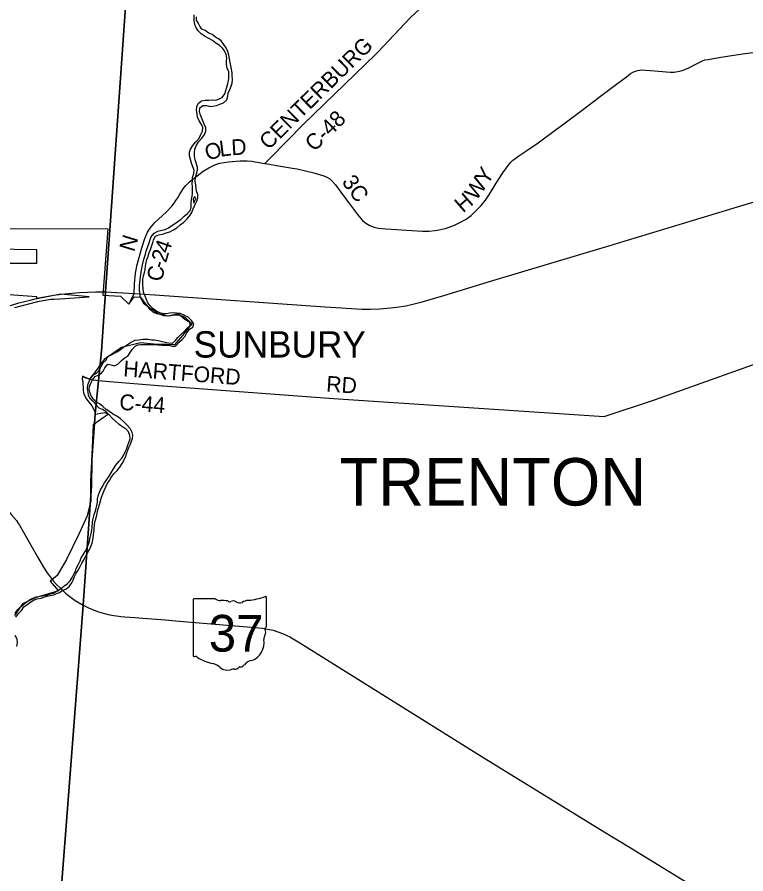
# Model space of a CAD drawing. Extents: x 1674899 to 2057726, y 653888 to 988278.
# Drawn here: x 1869524 to 1883353, y 809139 to 825391 of the extents above; entities that cross this region are included whole.
import ezdxf

# ---------------------------------------------------------------- set-up
doc = ezdxf.new("R2010")
doc.units = 0
for name, color, linetype in [('GM_X_Corporation', 7, 'Continuous'), ('GM_X_Corporation_Text', 7, 'Continuous'), ('GM_X_County_Road', 7, 'Continuous'), ('GM_X_County_Road_Text', 7, 'Continuous'), ('GM_X_Major_River', 7, 'Continuous'), ('GM_X_State_Location', 7, 'Continuous'), ('GM_X_State_Route', 7, 'Continuous'), ('GM_X_State_Shield', 7, 'Continuous'), ('GM_X_Township', 7, 'Continuous'), ('GM_X_Township_Text', 7, 'Continuous'), ('GM_X_US_Route', 7, 'Continuous'), ('SH_Data', 7, 'Continuous')]:
    doc.layers.add(name, color=color, linetype=linetype)

msp = doc.modelspace()

# ---------------------------------------------------------------- linework, layer by layer
at = {"layer": 'GM_X_Corporation'}
for points in [[(1868600, 821384), (1871245, 821376), (1871152, 820118), (1871483, 820096), (1871642, 819946), (1871748, 820085), (1871861, 820081), (1871921, 819965), (1872043, 819876), (1872199, 819766), (1872392, 819723), (1872582, 819770), (1872706, 819663), (1872848, 819582), (1872764, 819484), (1872661, 819350), (1872513, 819172), (1872369, 819183), (1872118, 819190), (1871863, 819214), (1871502, 819125), (1871177, 818898), (1870906, 818525), (1870848, 818543), (1870767, 818577), (1870760, 818526), (1870768, 818476), (1870779, 818314), (1870786, 818263), (1870803, 818212), (1870841, 818142), (1870892, 818081), (1870941, 818016), (1870984, 817932), (1871003, 817857), (1871186, 817888), (1871257, 817859), (1870965, 817659), (1870940, 817085), (1870914, 816591), (1870918, 816409), (1870920, 816216), (1870850, 815933), (1870694, 815581), (1870461, 815102), (1870281, 814797), (1870152, 814693), (1870300, 814517), (1870310, 814507), (1869865, 814374), (1869626, 814263), (1869472, 814042)], [(1869039, 820726), (1869899, 820726), (1869899, 820974), (1868600, 820997)], [(1869480, 819883), (1869917, 819994), (1870158, 820041), (1870228, 820041), (1870333, 820049), (1870889, 820088), (1870356, 820135), (1869899, 820044), (1869899, 820085), (1868844, 820159)]]:
    msp.add_lwpolyline(points, dxfattribs=at)
at = {"layer": 'GM_X_County_Road'}
for points in [[(1874227, 822615), (1874317, 822710), (1874959, 823358), (1876327, 824682), (1876365, 824720), (1876987, 825381), (1877524, 825893)], [(1872724, 822198), (1872792, 822267), (1872943, 822383), (1873056, 822467), (1873160, 822533), (1873276, 822590), (1873373, 822621), (1873532, 822646), (1873759, 822667), (1873891, 822665), (1873977, 822657), (1874044, 822647), (1874227, 822615), (1874315, 822599), (1874444, 822579), (1874557, 822560), (1874752, 822527), (1874836, 822512), (1875152, 822435), (1875346, 822380), (1875416, 822349), (1875458, 822321), (1875497, 822287), (1875565, 822207), (1875667, 822073), (1875831, 821849), (1875981, 821648), (1876039, 821575), (1876079, 821533), (1876143, 821482), (1876217, 821438), (1876297, 821406), (1876374, 821389), (1876519, 821376), (1876727, 821364), (1876913, 821349), (1877214, 821328), (1877336, 821330), (1877454, 821342), (1877534, 821356), (1877649, 821382), (1877722, 821406), (1877821, 821445), (1877928, 821496), (1878043, 821558), (1878138, 821626), (1878219, 821701), (1878331, 821818), (1878413, 821920), (1878486, 822032), (1878616, 822239), (1878743, 822436), (1878811, 822535), (1878842, 822578), (1878871, 822613), (1878895, 822642), (1878934, 822678), (1878967, 822704), (1879044, 822758), (1879197, 822860), (1879414, 823008), (1879735, 823245), (1879901, 823370), (1880245, 823625), (1880570, 823871), (1880847, 824079), (1881042, 824227), (1881087, 824259), (1881166, 824319), (1881210, 824345), (1881256, 824365), (1881305, 824380), (1881378, 824389), (1881448, 824388), (1881628, 824373), (1881838, 824352), (1881925, 824346), (1881993, 824349), (1882027, 824352), (1882091, 824364), (1882142, 824378), (1882259, 824424), (1882312, 824450), (1882368, 824481), (1882502, 824549), (1882531, 824563), (1882576, 824578), (1882637, 824590), (1882881, 824632), (1883086, 824662), (1883290, 824696), (1883493, 824720)], [(1871742, 820151), (1871742, 820151), (1871754, 820333), (1871771, 820532), (1871780, 820600), (1871796, 820672), (1871893, 821017), (1871942, 821170), (1871996, 821311), (1872051, 821390), (1872132, 821486), (1872206, 821558), (1872281, 821630), (1872352, 821694), (1872457, 821804), (1872502, 821861), (1872537, 821910), (1872571, 821965), (1872610, 822031), (1872673, 822132), (1872724, 822198)], [(1871678, 820004), (1871742, 820151)], [(1871277, 818480), (1872206, 818406), (1875525, 818156), (1880663, 817814), (1881619, 818131), (1884362, 819111), (1887858, 818871), (1889457, 818761), (1891623, 818604), (1892346, 818560), (1895326, 818344), (1897532, 818224), (1897769, 818211), (1897801, 818204), (1897822, 818179)], [(1870769, 818573), (1870822, 818549), (1870854, 818540), (1870866, 818536)], [(1870866, 818536), (1870906, 818522), (1870968, 818509), (1871065, 818497), (1871277, 818480)]]:
    msp.add_lwpolyline(points, dxfattribs=at)
at = {"layer": 'GM_X_Major_River'}
for points in [[(1873229, 824950), (1873161, 824988), (1873091, 825023), (1873019, 825073), (1872958, 825131), (1872914, 825200), (1872894, 825250), (1872885, 825318), (1872883, 825370), (1872881, 825436)], [(1873291, 825009), (1873225, 825062), (1873159, 825088), (1873094, 825135), (1873032, 825163), (1872988, 825217), (1872960, 825284), (1872929, 825334), (1872929, 825398)], [(1872770, 819699), (1872741, 819714), (1872684, 819745), (1872616, 819770), (1872550, 819775), (1872490, 819779), (1872424, 819777), (1872351, 819764), (1872301, 819764), (1872232, 819780), (1872166, 819811), (1872104, 819859), (1872042, 819922), (1872005, 819972), (1871973, 820044), (1871951, 820098), (1871924, 820173), (1871916, 820243), (1871911, 820311), (1871909, 820367), (1871911, 820419), (1871920, 820483), (1871938, 820549), (1871952, 820601), (1871961, 820667), (1871973, 820739), (1871987, 820791), (1872010, 820853), (1872026, 820907), (1872057, 820985), (1872079, 821061), (1872099, 821113), (1872114, 821167), (1872152, 821235), (1872214, 821264), (1872280, 821276), (1872355, 821296), (1872423, 821319), (1872491, 821355), (1872555, 821397), (1872618, 821449), (1872688, 821504), (1872752, 821562), (1872805, 821634), (1872837, 821686), (1872862, 821754), (1872894, 821824), (1872936, 821897), (1872951, 821963), (1872953, 822026), (1872926, 822090), (1872922, 822140), (1872918, 822208), (1872905, 822276), (1872909, 822348), (1872927, 822420), (1872948, 822490), (1872950, 822544), (1872905, 822683), (1872891, 822759), (1872888, 822823), (1872896, 822889), (1872923, 822951), (1872963, 823025), (1873026, 823094), (1873078, 823162), (1873104, 823230), (1873107, 823292), (1873075, 823359), (1873047, 823423), (1873022, 823487), (1873000, 823553), (1872987, 823603), (1872993, 823669), (1873047, 823713), (1873117, 823717), (1873185, 823696), (1873235, 823702), (1873307, 823716), (1873372, 823737), (1873440, 823767), (1873502, 823823), (1873520, 823889), (1873531, 823949), (1873563, 824021), (1873586, 824081), (1873602, 824139), (1873610, 824209), (1873607, 824283), (1873603, 824335), (1873594, 824405), (1873578, 824471), (1873564, 824533), (1873557, 824602), (1873543, 824672), (1873524, 824742), (1873492, 824810), (1873444, 824874), (1873395, 824939), (1873343, 824981), (1873291, 825009)], [(1872672, 819714), (1872640, 819726), (1872577, 819735), (1872509, 819737), (1872439, 819725), (1872370, 819718), (1872307, 819723), (1872241, 819750), (1872177, 819763), (1872110, 819789), (1872052, 819840), (1872008, 819896), (1871954, 819964), (1871909, 820030), (1871859, 820093), (1871852, 820161), (1871848, 820221), (1871848, 820295), (1871851, 820355), (1871857, 820405), (1871863, 820471), (1871876, 820541), (1871882, 820595), (1871895, 820653), (1871909, 820717), (1871923, 820773), (1871940, 820839), (1871958, 820897), (1871972, 820951), (1872001, 821023), (1872023, 821093), (1872040, 821155), (1872070, 821225), (1872122, 821293), (1872195, 821333), (1872267, 821348), (1872335, 821362), (1872399, 821394), (1872461, 821439), (1872512, 821473), (1872574, 821515), (1872638, 821561), (1872693, 821616), (1872757, 821666), (1872805, 821724), (1872826, 821788), (1872828, 821860), (1872835, 821930), (1872843, 821994), (1872849, 822046), (1872852, 822110), (1872852, 822170), (1872846, 822234), (1872849, 822284), (1872853, 822346), (1872879, 822422), (1872886, 822486), (1872858, 822551), (1872833, 822619), (1872817, 822691), (1872795, 822759), (1872796, 822829), (1872814, 822889), (1872857, 822955), (1872909, 823021), (1872969, 823085), (1873006, 823155), (1873040, 823229), (1873047, 823295), (1873023, 823357), (1872977, 823425), (1872950, 823493), (1872938, 823557), (1872929, 823622), (1872933, 823698), (1872959, 823752), (1873022, 823803), (1873092, 823817), (1873162, 823817), (1873228, 823822), (1873292, 823818), (1873344, 823836), (1873414, 823869), (1873465, 823937), (1873483, 823999), (1873502, 824065), (1873522, 824133), (1873532, 824185), (1873539, 824235), (1873543, 824287), (1873539, 824353), (1873508, 824424), (1873498, 824494), (1873498, 824560), (1873501, 824612), (1873491, 824682), (1873460, 824754), (1873420, 824805), (1873358, 824857), (1873292, 824895), (1873229, 824950)], [(1872881, 821974), (1872865, 821936), (1872876, 821862)], [(1872876, 821862), (1872892, 821894), (1872915, 821942), (1872905, 821978), (1872881, 821974)], [(1870946, 815711), (1870947, 815731), (1870953, 815801), (1870963, 815855), (1870974, 815907), (1870988, 815959), (1871002, 816009), (1871023, 816077), (1871037, 816127), (1871047, 816191), (1871050, 816255), (1871060, 816307), (1871080, 816359), (1871109, 816421), (1871147, 816487), (1871185, 816555), (1871226, 816619), (1871268, 816683), (1871309, 816747), (1871353, 816823), (1871395, 816891), (1871456, 816961), (1871510, 817022), (1871551, 817086), (1871575, 817144), (1871597, 817198), (1871626, 817270), (1871644, 817324), (1871670, 817390), (1871663, 817455), (1871639, 817527), (1871587, 817581), (1871528, 817614), (1871460, 817664), (1871392, 817729), (1871327, 817781), (1871273, 817848), (1871209, 817910), (1871144, 817949), (1871078, 817971), (1871022, 818038), (1870968, 818100), (1870917, 818141), (1870877, 818215), (1870871, 818285), (1870858, 818347), (1870866, 818413), (1870889, 818477), (1870917, 818545), (1870959, 818597), (1871032, 818639), (1871088, 818701), (1871116, 818769), (1871157, 818833), (1871215, 818883), (1871241, 818951), (1871300, 818976), (1871356, 819008), (1871418, 819040), (1871478, 819082), (1871542, 819131), (1871619, 819181), (1871675, 819217), (1871763, 819264), (1871835, 819270), (1871909, 819279), (1871959, 819281), (1872011, 819279), (1872077, 819268), (1872129, 819270), (1872203, 819256), (1872279, 819239), (1872333, 819227), (1872399, 819212), (1872473, 819208), (1872527, 819256), (1872576, 819314), (1872626, 819362), (1872688, 819423), (1872745, 819485), (1872809, 819541), (1872803, 819609), (1872734, 819672), (1872672, 819714)], [(1870961, 815478), (1870967, 815510), (1870976, 815578), (1870984, 815644), (1870986, 815696), (1870995, 815746), (1871001, 815808), (1871015, 815875), (1871034, 815943), (1871050, 816019), (1871069, 816085), (1871087, 816145), (1871107, 816215), (1871128, 816283), (1871152, 816351), (1871173, 816409), (1871205, 816479), (1871235, 816537), (1871274, 816603), (1871310, 816655), (1871362, 816725), (1871423, 816788), (1871473, 816854), (1871516, 816926), (1871554, 816992), (1871584, 817062), (1871603, 817124), (1871623, 817174), (1871643, 817230), (1871674, 817290), (1871694, 817344), (1871712, 817396), (1871717, 817464), (1871709, 817514), (1871667, 817589), (1871608, 817655), (1871544, 817718), (1871477, 817780), (1871417, 817821), (1871355, 817855), (1871285, 817904), (1871216, 817950), (1871150, 818007), (1871084, 818055), (1871020, 818092), (1870965, 818148), (1870921, 818221), (1870903, 818283), (1870894, 818333), (1870900, 818383), (1870922, 818447), (1870955, 818509), (1871007, 818575), (1871059, 818597), (1871113, 818627), (1871154, 818678), (1871186, 818738), (1871245, 818810), (1871304, 818796), (1871370, 818773), (1871433, 818807), (1871505, 818877), (1871573, 818937), (1871623, 818960), (1871670, 819030), (1871706, 819084), (1871765, 819150), (1871815, 819172), (1871865, 819182), (1871927, 819181), (1872001, 819179), (1872065, 819180), (1872133, 819178), (1872197, 819174), (1872269, 819171), (1872337, 819169), (1872401, 819168), (1872469, 819148), (1872529, 819152), (1872603, 819229), (1872655, 819277), (1872710, 819341), (1872746, 819405), (1872793, 819471), (1872861, 819511), (1872879, 819573), (1872834, 819635), (1872770, 819699)], [(1869485, 814085), (1869539, 814155), (1869590, 814207), (1869644, 814249), (1869708, 814302), (1869776, 814350), (1869841, 814376), (1869891, 814396), (1869965, 814409), (1870033, 814421), (1870087, 814428), (1870157, 814448), (1870207, 814462), (1870283, 814508), (1870348, 814545), (1870412, 814595), (1870476, 814643), (1870533, 814699), (1870569, 814762), (1870599, 814822), (1870630, 814884), (1870642, 814934), (1870680, 815000), (1870719, 815076), (1870741, 815134), (1870775, 815188), (1870814, 815256), (1870850, 815328), (1870877, 815392), (1870895, 815452), (1870911, 815522), (1870926, 815594), (1870940, 815660), (1870946, 815711)], [(1869498, 814009), (1869549, 814079), (1869605, 814135), (1869652, 814206), (1869724, 814258), (1869786, 814302), (1869850, 814334), (1869900, 814353), (1869977, 814371), (1870029, 814385), (1870095, 814406), (1870151, 814418), (1870219, 814434), (1870269, 814457), (1870325, 814479), (1870375, 814505), (1870452, 814545), (1870518, 814594), (1870560, 814658), (1870585, 814710), (1870615, 814780), (1870647, 814840), (1870682, 814898), (1870718, 814972), (1870751, 815030), (1870797, 815102), (1870825, 815172), (1870862, 815228), (1870888, 815280), (1870920, 815350), (1870945, 815414), (1870961, 815478)], [(1869517, 813453), (1869532, 813526), (1869524, 813590), (1869486, 813662)]]:
    msp.add_lwpolyline(points, dxfattribs=at)
at = {"layer": 'GM_X_State_Route'}
for points in [[(1869071, 816377), (1869420, 815948), (1869509, 815839), (1869530, 815808), (1869534, 815802)], [(1869534, 815802), (1869567, 815752), (1869669, 815577), (1869812, 815327), (1869906, 815164)], [(1869906, 815164), (1869910, 815156), (1870025, 814958), (1870094, 814847), (1870207, 814697)], [(1870207, 814697), (1870211, 814693), (1870271, 814626), (1870352, 814549), (1870443, 814463), (1870476, 814436), (1870628, 814325), (1870779, 814239), (1870889, 814182), (1871068, 814112), (1871253, 814061), (1871361, 814039), (1871455, 814026)], [(1871455, 814026), (1871491, 814021), (1871569, 814014), (1871759, 814000), (1871910, 813989), (1872340, 813955), (1872527, 813939), (1873053, 813896), (1874044, 813812), (1874182, 813797), (1874274, 813782), (1874381, 813759), (1874562, 813699), (1874700, 813634), (1874793, 813581), (1874892, 813523), (1878383, 811338), (1880549, 810005), (1880810, 809846), (1880939, 809769), (1881144, 809643), (1882507, 808811)]]:
    msp.add_lwpolyline(points, dxfattribs=at)
at = {"layer": 'GM_X_State_Shield'}
for p, q in [((1872862, 814337), (1872862, 813281)), ((1873283, 814356), (1872876, 814356)), ((1874254, 813829), (1874254, 814382)), ((1874254, 813829), (1874254, 813829))]:
    msp.add_line(p, q, dxfattribs=at)
for centre, radius, start, end in [((1873758, 815796), 1476, 275.8445, 288.9065), ((1874239, 814384), 15.5, 351.8621, 97.738), ((1872878, 814340), 16.1, 98.1301, 188.1301), ((1873381, 814478), 156, 231.6195, 271.1119), ((1873432, 813762), 562, 80.4867, 94.9883), ((1873560, 814345), 45.1, 219.7921, 297.1024), ((1873626, 814223), 93.8, 54.4667, 119.1411), ((1873747, 814390), 113, 233.8562, 294.8282), ((1873947, 814033), 297, 97.3462, 120.7689), ((1874251, 813788), 24, 107.944, 210.337), ((1874098, 813719), 144, 340.033, 23.6496), ((1874238, 813827), 16.6, 289.6038, 7.7341), ((1873841, 813527), 369, 292.3089, 8.9858), ((1874310, 813598), 105, 136.8065, 186.9296), ((1872878, 813278), 16.3, 171.9584, 258.3066), ((1872881, 813387), 124, 267.339, 280.6039), ((1872906, 813220), 44.8, 29.7484, 93.2717), ((1873471, 814169), 1066, 240.4129, 257.1985), ((1873153, 812806), 334, 47.1842, 75.836), ((1873740, 813178), 119, 282.8732, 323.2771), ((1873997, 812984), 202, 94.4031, 142.5768), ((1873514, 813215), 212, 230.7004, 286.2918), ((1873637, 812849), 174, 85.6951, 111.2099), ((1873652, 813135), 113, 268.777, 315.5493), ((1873754, 813033), 31.8, 65.7517, 132.6484)]:
    msp.add_arc(centre, radius, start, end, dxfattribs=at)
at = {"layer": 'GM_X_Township'}
for points in [[(1854821, 832136), (1858606, 831851), (1859467, 831803), (1861106, 831707), (1868637, 831266), (1870943, 831158), (1871301, 831135), (1871965, 831096), (1871199, 820179), (1871124, 819057), (1871065, 818497), (1871003, 817857), (1870943, 816996), (1870933, 816495), (1870903, 816053), (1870779, 814239), (1870309, 808163)], [(1870309, 808163), (1870779, 814239), (1870903, 816053), (1870933, 816495), (1870943, 816996), (1871003, 817857), (1871065, 818497), (1871124, 819057), (1871199, 820179), (1871965, 831096), (1873866, 830983), (1874715, 830911), (1874782, 830900), (1876113, 830808), (1881808, 830417), (1885186, 830186)]]:
    msp.add_lwpolyline(points, dxfattribs=at)
at = {"layer": 'GM_X_US_Route'}
for points in [[(1871153, 820180), (1871199, 820179), (1871742, 820151), (1872137, 820124), (1875367, 819897), (1876072, 819853), (1876232, 819852), (1876406, 819857), (1876545, 819867), (1876727, 819890), (1876899, 819917), (1877009, 819941), (1877209, 819989), (1877624, 820113), (1878554, 820394), (1880687, 821035), (1883192, 821790), (1886098, 822667)], [(1869772, 820024), (1869935, 820064), (1870218, 820115), (1870358, 820133), (1870708, 820169), (1871013, 820182), (1871153, 820180)], [(1868423, 819513), (1868530, 819569), (1868780, 819692), (1868932, 819756), (1869103, 819824), (1869240, 819873), (1869556, 819971), (1869772, 820024)]]:
    msp.add_lwpolyline(points, dxfattribs=at)
at = {"layer": 'SH_Data'}
for points in [[(1871153, 820180), (1871199, 820179), (1871742, 820151), (1872137, 820124), (1875367, 819897), (1876072, 819853), (1876232, 819852), (1876406, 819857), (1876545, 819867), (1876727, 819890), (1876899, 819917), (1877009, 819941), (1877209, 819989), (1877624, 820113), (1878554, 820394), (1880687, 821035), (1883192, 821790), (1886098, 822667)], [(1869772, 820024), (1869935, 820064), (1870218, 820115), (1870358, 820133), (1870708, 820169), (1871013, 820182), (1871153, 820180)], [(1868423, 819513), (1868530, 819569), (1868780, 819692), (1868932, 819756), (1869103, 819824), (1869240, 819873), (1869556, 819971), (1869772, 820024)]]:
    msp.add_lwpolyline(points, dxfattribs=at)

# ---------------------------------------------------------------- texts
at = {"layer": 'GM_X_Corporation_Text'}
msp.add_text('SUNBURY', height=500, rotation=0, dxfattribs=at).set_placement((1872874, 818933))
at = {"layer": 'GM_X_County_Road_Text'}
for s, rotation, p in [('CENTERBURG', 44.4906, (1874297, 822859)), ('C-48', 44.5212, (1875164, 822826)), ('O', 18.5087, (1873143, 822662)), ('L', 7.0937, (1873378, 822742)), ('D', 3.3568, (1873596, 822770)), ('Y', 57.3674, (1878447, 822192)), ('3C', 305.8117, (1875675, 822264)), ('W', 54.357, (1878235, 821895)), ('H', 41.092, (1877986, 821666)), ('N', 72.8116, (1871742, 820924)), ('4', 70.7767, (1872401, 820892)), ('2', 73.6736, (1872350, 820718)), ('-', 73.8959, (1872316, 820600)), ('C', 81.7518, (1872283, 820367)), ('HARTFORD', 355.6599, (1871531, 818578)), ('RD', 356.1234, (1875383, 818288)), ('C-44', 355.5487, (1871455, 817945))]:
    msp.add_text(s, height=300, rotation=rotation, dxfattribs=at).set_placement(p)
at = {"layer": 'GM_X_State_Location'}
msp.add_text('37', height=1, rotation=0, dxfattribs=at).set_placement((1873291, 813666))
for s in ['s', 'r']:
    msp.add_text(s, height=1, dxfattribs=at).set_placement((1873542, 813739))
at = {"layer": 'GM_X_State_Shield'}
msp.add_text('37', height=696.1, dxfattribs=at).set_placement((1873162, 813355))
at = {"layer": 'GM_X_Township_Text'}
msp.add_text('TRENTON', height=900, rotation=0, dxfattribs=at).set_placement((1875642, 816126))

doc.saveas('drawing.dxf')
